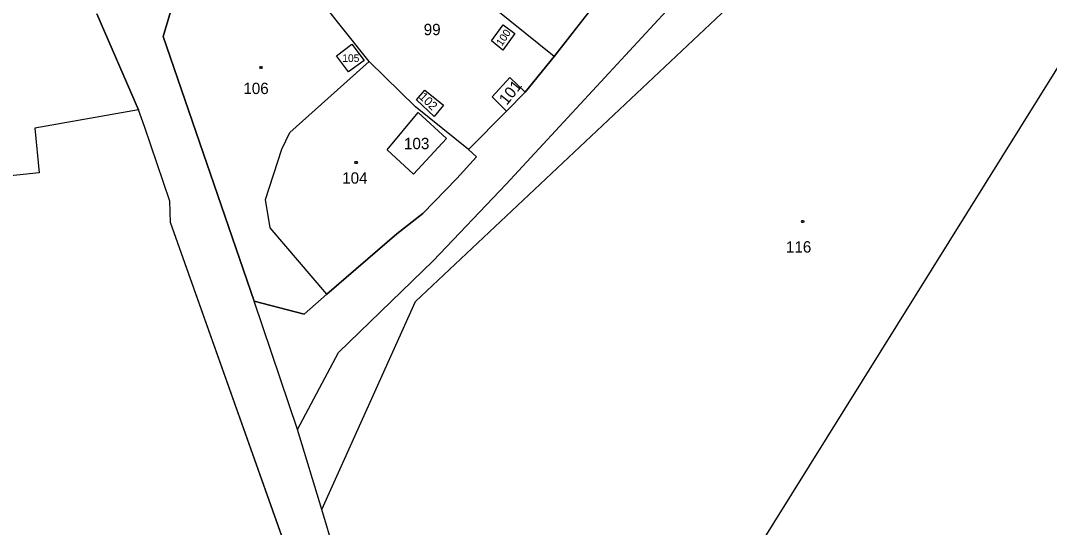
# Model space of a CAD drawing. Extents: x -841286 to -834997, y -1020681 to -1017810.
# Drawn here: x -838539 to -838385, y -1019346.4 to -1019270.6 of the extents above; entities that cross this region are included whole.
import ezdxf

# ---------------------------------------------------------------- set-up
doc = ezdxf.new("R2010")
doc.units = 0
for name, color, linetype in [('OVNE_POP', 7, 'Continuous'), ('OVNE_PRE', 7, 'Continuous'), ('OVNE_SET', 7, 'Continuous'), ('OVNI_SET', 7, 'Continuous')]:
    doc.layers.add(name, color=color, linetype=linetype)

msp = doc.modelspace()

# ---------------------------------------------------------------- linework, layer by layer
at = {"layer": 'OVNE_POP'}
for points in [[(-838502.94, -1019277.47), (-838502.85, -1019277.62), (-838502.94, -1019277.77), (-838503.12, -1019277.77), (-838503.21, -1019277.62), (-838503.12, -1019277.47)], [(-838488.7, -1019291.67), (-838488.61, -1019291.82), (-838488.7, -1019291.97), (-838488.88, -1019291.97), (-838488.97, -1019291.82), (-838488.88, -1019291.67)], [(-838421.85, -1019300.49), (-838421.76, -1019300.64), (-838421.85, -1019300.79), (-838422.03, -1019300.79), (-838422.12, -1019300.64), (-838422.03, -1019300.49)]]:
    msp.add_lwpolyline(points, close=True, dxfattribs=at)
at = {"layer": 'OVNE_SET'}
for p, q in [((-838467.55, -1019411.98), (-838342.17, -1019210.92)), ((-838466.36, -1019295.07), (-838425.35, -1019250.72)), ((-838479.91, -1019312.64), (-838416.24, -1019252.7)), ((-838459.17, -1019275.97), (-838484.58, -1019255.43)), ((-838450.12, -1019264.38), (-838459.17, -1019275.97)), ((-838517.7, -1019272.98), (-838515.97, -1019267.23)), ((-838486.87, -1019276.7), (-838493.71, -1019268.09)), ((-838527.61, -1019269.56), (-838521.36, -1019283.94)), ((-838468.52, -1019273.62), (-838466.8, -1019271.2)), ((-838466.8, -1019271.2), (-838465.02, -1019272.52)), ((-838504.06, -1019312.59), (-838517.7, -1019272.98)), ((-838465.02, -1019272.52), (-838466.82, -1019275.01)), ((-838491.74, -1019275.84), (-838489.43, -1019274.1)), ((-838489.43, -1019274.1), (-838487.6, -1019276.55)), ((-838466.82, -1019275.01), (-838468.52, -1019273.62)), ((-838489.93, -1019278.28), (-838491.74, -1019275.84)), ((-838487.6, -1019276.55), (-838489.93, -1019278.28)), ((-838459.17, -1019275.97), (-838463.48, -1019281.28)), ((-838498.71, -1019287.35), (-838486.87, -1019276.7)), ((-838479.92, -1019283.48), (-838486.87, -1019276.7)), ((-838468.44, -1019282.02), (-838465.77, -1019279.1)), ((-838465.77, -1019279.1), (-838463.48, -1019281.28)), ((-838479.76, -1019282.47), (-838478.51, -1019280.98)), ((-838478.51, -1019280.98), (-838475.74, -1019283.23)), ((-838477.1, -1019284.93), (-838479.76, -1019282.47)), ((-838466.29, -1019284.14), (-838468.44, -1019282.02)), ((-838463.48, -1019281.28), (-838466.29, -1019284.14)), ((-838521.36, -1019283.94), (-838536.88, -1019286.69)), ((-838520.49, -1019286.46), (-838521.36, -1019283.94)), ((-838484.17, -1019289.94), (-838479.5, -1019284.33)), ((-838471.97, -1019289.87), (-838479.92, -1019283.48)), ((-838479.5, -1019284.33), (-838475.28, -1019288.21)), ((-838475.74, -1019283.23), (-838477.1, -1019284.93)), ((-838466.29, -1019284.14), (-838471.97, -1019289.87)), ((-838536.88, -1019286.69), (-838536.26, -1019293.35)), ((-838516.69, -1019297.63), (-838520.49, -1019286.46)), ((-838499.91, -1019289.82), (-838498.71, -1019287.35)), ((-838475.28, -1019288.21), (-838480.21, -1019293.58)), ((-838502.36, -1019297.38), (-838499.91, -1019289.82)), ((-838480.21, -1019293.58), (-838484.17, -1019289.94)), ((-838471.97, -1019289.87), (-838470.76, -1019290.99)), ((-838470.76, -1019290.99), (-838473.74, -1019294.21)), ((-838536.26, -1019293.35), (-838555.84, -1019295.51)), ((-838473.74, -1019294.21), (-838478.82, -1019299.46)), ((-838477.24, -1019306.52), (-838466.36, -1019295.07)), ((-838516.57, -1019300.78), (-838516.69, -1019297.63)), ((-838501.66, -1019301.59), (-838502.36, -1019297.38)), ((-838478.82, -1019299.46), (-838482.7, -1019302.48)), ((-838489.78, -1019376.26), (-838516.57, -1019300.78)), ((-838493.2, -1019311.5), (-838501.66, -1019301.59)), ((-838482.7, -1019302.48), (-838493.2, -1019311.5)), ((-838491.43, -1019320.25), (-838477.24, -1019306.52)), ((-838493.2, -1019311.5), (-838496.57, -1019314.52)), ((-838497.56, -1019331.78), (-838504.06, -1019312.59)), ((-838496.57, -1019314.52), (-838504.06, -1019312.59)), ((-838493.94, -1019343.74), (-838479.91, -1019312.64)), ((-838497.56, -1019331.78), (-838491.43, -1019320.25)), ((-838493.94, -1019343.74), (-838497.56, -1019331.78)), ((-838490.15, -1019356.24), (-838493.94, -1019343.74))]:
    msp.add_line(p, q, dxfattribs=at)
at = {"layer": 'OVNI_SET'}
for points in [[(-838515.97, -1019267.23), (-838517.7, -1019272.98), (-838504.06, -1019312.59), (-838496.57, -1019314.52), (-838493.2, -1019311.5), (-838482.7, -1019302.48), (-838478.82, -1019299.46), (-838473.74, -1019294.21), (-838470.76, -1019290.99), (-838471.97, -1019289.87), (-838466.29, -1019284.14), (-838463.48, -1019281.28), (-838459.17, -1019275.97), (-838450.12, -1019264.38)], [(-838489.78, -1019376.26), (-838516.57, -1019300.78), (-838516.69, -1019297.63), (-838520.49, -1019286.46), (-838521.36, -1019283.94), (-838527.61, -1019269.56)]]:
    msp.add_lwpolyline(points, dxfattribs=at)

# ---------------------------------------------------------------- texts
at = {"layer": 'OVNE_PRE'}
for s, height, p in [('99', 1.7, (-838478.68, -1019272.77)), ('105', 1.14, (-838490.86, -1019276.78)), ('106', 1.7, (-838505.68, -1019281.58)), ('103', 1.7, (-838481.63, -1019289.83)), ('104', 1.7, (-838490.88, -1019294.99)), ('116', 1.7, (-838424.45, -1019305.3))]:
    msp.add_text(s, height=height, dxfattribs=at).set_placement(p)
for s, height, rotation, p in [('100', 1.14, 55.978, (-838466.99, -1019274.5)), ('101', 1.7, 51.2797, (-838466.24, -1019283.34)), ('102', 1.3, 315.6424, (-838479.47, -1019282.1))]:
    msp.add_text(s, height=height, rotation=rotation, dxfattribs=at).set_placement(p)

doc.saveas('drawing.dxf')
